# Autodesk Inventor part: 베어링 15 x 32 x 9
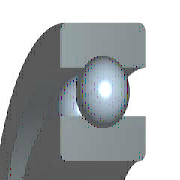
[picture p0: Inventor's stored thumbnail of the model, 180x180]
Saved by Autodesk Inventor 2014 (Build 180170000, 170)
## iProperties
IsCustomPart: 0
Created: 2012-02
Part Number: 베어링 15 x 32 x 9
Material: 강철, 연강
Description: 깊은 그루브 볼 베어링
Document SubType Name: Modeling
Standard: KS B 2023
Designer: mduedu
Standards Organization: KS
Language: ko-KR
Size Designation: 6002 - 15 x 32 x 9
Categories: <MemberInstance><Categories><Category DisplayName="샤프트 부품" InternalName="7f7aeb1f-a693-4053-b835-cee3144e0d98" Mnemonic="SHFT"><Category DisplayName="베어링" Inter
Density: 1 g/cm^3
Appearance: Steel
Author: mduedu
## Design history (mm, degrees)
sketch "스케치" dims "d0" = 4.42 (= -0.26 x WD + 0.26 x BD)
  geometry: L1 (2.29, 11.75)-(6.71, 11.75); L2 (4.5, 11.75)-(4.5, 9.54); L3 (4.5, 11.75)-(4.5, 13.96); L4 (2.858, 10.271)-(0, 10.271); L5 (0, 7.5)-(9, 7.5); L6 (2.858, 13.229)-(0, 13.229); L7 (0, 16)-(9, 16); L8 (9, 7.5)-(9, 10.271); L9 (6.142, 10.271)-(9, 10.271); L10 (6.142, 13.229)-(9, 13.229); L11 (9, 16)-(9, 13.229); L12 (-1.4, 0)-(8.4, 0) reference; L13 (0, -0.3)-(0, 5.3) reference
  constraints: 22 end point, 4 point on line, 2 collinear, 2 perpendicular, 2 symmetric about line, 1 midpoint, 1 parallel, 14 other
  dimensions: "d9" = 15 diameter of L5 L12 (= WD); "d11" = 32 diameter of L7 L12 (= BD); "d12" = 9 distance between parallel lines of L8 L13 (= KB); "d13" = 20.542 diameter of L9 L12 (= 0.326 x BD + 0.674 x WD)
revolve "본체" stored, may be unused: angle "d6" = 90 deg
revolve "볼" stored, may be unused: angle "d7" = 90 deg
pattern_circular "IDS_ARRAYBALL[SIMPL:T]" dims angle "d3" = 360 deg
body "Solid1"
fillet "모깎기1" dims "d1" = 0.3 (= KRS)
other parameters: "WD" = 15 [user parameter; used in 5 equation terms], "BD" = 32 [user parameter; used in 5 equation terms], "KB" = 9 [user parameter; used in 1 equation term], "KRS" = 0.3 [user parameter; used in 1 equation term], "d4" = 0, "d5" = 0, "d8" = 0, "d14" = 0, "d15" = 0, "BBA" = 0 [user parameter], "BC0" = 2850000 [user parameter], "BC" = 5590000 [user parameter], "BR" = 16 (= 0.5 x BD) [user parameter], "WR" = 7.5 (= 0.5 x WD) [user parameter]
